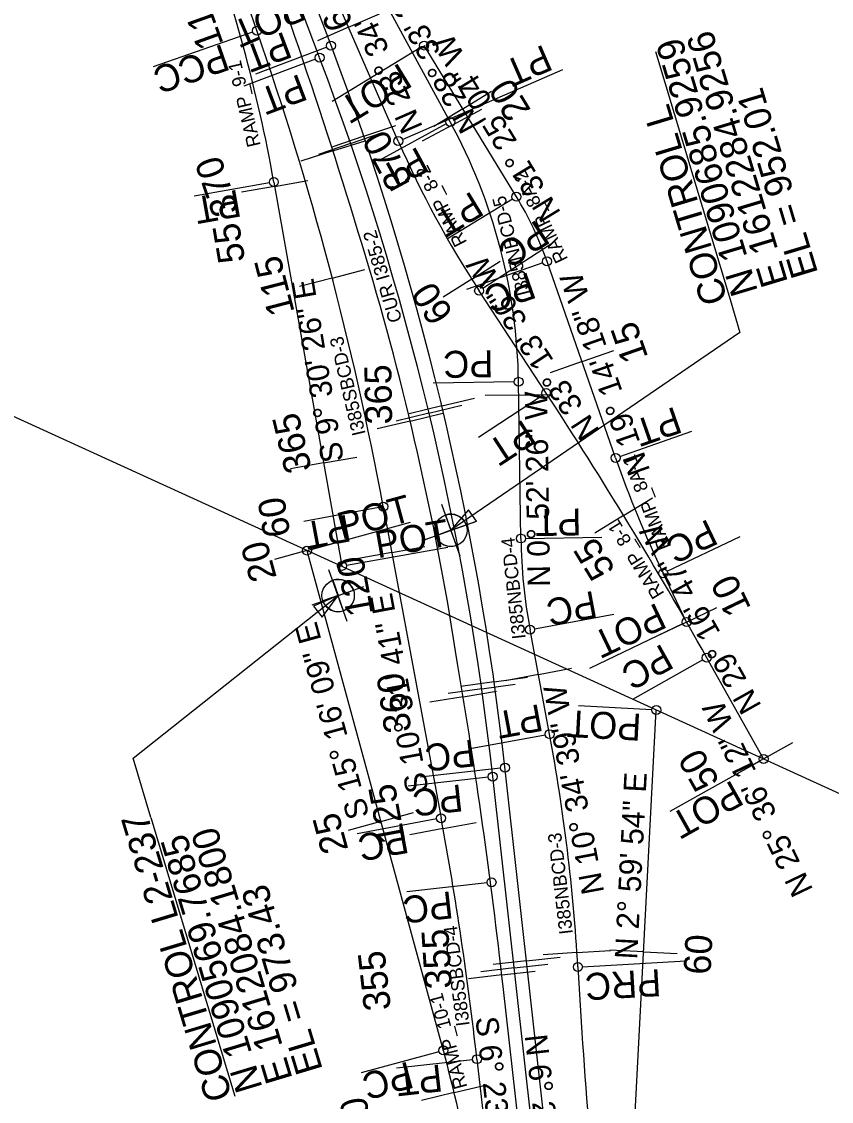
# Model space of a CAD drawing. Extents: x 1603447 to 1622636, y 1083818 to 1103958.
# Drawn here: x 1611521 to 1612962, y 1089669 to 1091591 of the extents above; entities that cross this region are included whole.
import ezdxf

# ---------------------------------------------------------------- set-up
doc = ezdxf.new("R2010")
doc.units = 0
for name, color, linetype in [('Level 1', 7, 'Continuous'), ('RD_HC_Points', 7, 'Continuous'), ('RD_HC_SUR_Bearing_TX400', 7, 'Continuous'), ('RD_HC_SUR_CL400', 7, 'Continuous'), ('RD_HC_SUR_PC_PT_400', 7, 'Continuous'), ('RD_HC_SUR_Tic400', 7, 'Continuous'), ('RD_HC_SUR_TX_Sta400', 7, 'Continuous'), ('RD_SHT_Misc1', 7, 'Continuous'), ('RD_TX_Misc1', 7, 'Continuous')]:
    doc.layers.add(name, color=color, linetype=linetype)

msp = doc.modelspace()

# ---------------------------------------------------------------- linework, layer by layer
at = {"layer": 'RD_HC_Points'}
for p, q in [((1612649, 1091538.2), (1612781.9, 1091096.5)), ((1611750.7, 1090174.9), (1611900, 1089678.9))]:
    msp.add_line(p, q, dxfattribs=at)
for points in [[(1612781.9, 1091096.5), (1612799.5, 1091038.1), (1612284.9, 1090685.9)], [(1611750.7, 1090174.9), (1611719, 1090280.2), (1612084.2, 1090569.8)]]:
    msp.add_lwpolyline(points, dxfattribs=at)
for points in [[(1612316.2, 1090722.4), (1612284.9, 1090685.9), (1612330.2, 1090701.9)], [(1612055.6, 1090531.2), (1612084.2, 1090569.8), (1612040.1, 1090550.7)]]:
    msp.add_lwpolyline(points, close=True, dxfattribs=at)
at = {"layer": 'RD_HC_SUR_CL400'}
for p, q in [((1612051.1, 1091527.2), (1611564.1, 1092814.8)), ((1612071.1, 1091550.5), (1611593.4, 1092813.6)), ((1612283.8, 1091412.9), (1612117.9, 1091717.6)), ((1612191.2, 1091378.6), (1612063.1, 1091672.2)), ((1612401.6, 1091279.6), (1612237.2, 1091548.8)), ((1611969.7, 1091305.8), (1612090.9, 1090622.6)), ((1613356.7, 1090043.6), (1610810.9, 1091205.6)), ((1612578.1, 1090814.8), (1612456, 1091164.6)), ((1612454.5, 1090930.1), (1612335.2, 1091112.3)), ((1612409.5, 1090671.3), (1612405.3, 1090950.2)), ((1612164.4, 1090728), (1612267.5, 1090173.4)), ((1612028.5, 1090649.9), (1612271.4, 1089760)), ((1612704.5, 1090522.6), (1612662.8, 1090609.5)), ((1612460.6, 1090323), (1612425.8, 1090508.9)), ((1612841.5, 1090278.8), (1612740.4, 1090459.1)), ((1612608.3, 1089558.3), (1612650.6, 1090365.9)), ((1612533.6, 1088900.6), (1612380.9, 1090265.1)), ((1612510.5, 1088898), (1612359.5, 1090247.4)), ((1612487.4, 1088895.4), (1612377.9, 1089874.1)), ((1612331.3, 1089744.5), (1612349.6, 1089581.2))]:
    msp.add_line(p, q, dxfattribs=at)
for centre, radius, start, end in [((1602552.7, 1088307.1), 10000, 16.52176, 20.71665), ((1602552.7, 1088307.1), 9939.5, 19.19672, 20.71665), ((1609311.2, 1090834.2), 2700, 10.058, 20.5018), ((1606462.1, 1089668.2), 5800, 10.52808, 19.19672), ((1607113.8, 1089675.6), 5300, 6.3858, 20.7167), ((1607115.5, 1089660.5), 5276.8, 6.3858, 20.7167), ((1611405.4, 1090934.9), 1000, 0.8738, 28.5554), ((1613841, 1092098.6), 1800, 203.5791, 213.2266), ((1611889.5, 1090966.9), 600, 19.2382, 31.4178), ((1607115.5, 1089660.5), 5240.8, 8.6501, 16.5218), ((1605762.5, 1086546.5), 8000, 29.27962, 33.2266), ((1614466.4, 1091473.8), 2000, 199.2382, 205.6034), ((1613374.4, 1090686.1), 965, 180.8738, 190.5776), ((1602439.9, 1088761.9), 10000, 6.3858, 9.71157), ((1609241.2, 1089721.8), 3275, 3.2705, 10.5776), ((1606368.5, 1089077.1), 6000, 6.3858, 10.52808), ((1623992.1, 1090564.7), 11500, 183.27051, 186.3858), ((1609859.7, 1089101.6), 2500, 10.1713, 15.269)]:
    msp.add_arc(centre, radius, start, end, dxfattribs=at)
at = {"layer": 'RD_HC_SUR_PC_PT_400'}
for p, q in [((1611932, 1091572.7), (1611755, 1091511.1)), ((1612063.8, 1091545.8), (1611936.8, 1091497.8)), ((1612230.4, 1091544.6), (1612073.8, 1091449)), ((1612043.6, 1091524.3), (1611916.5, 1091476.3)), ((1612198.6, 1091381.8), (1612484.1, 1091506.4)), ((1612276.7, 1091409.1), (1612157.4, 1091344.2)), ((1611961.9, 1091304.4), (1611828.1, 1091280.7)), ((1612394.7, 1091275.5), (1612278.8, 1091204.7)), ((1612341.9, 1091116.7), (1612462.2, 1091195.4)), ((1612448.5, 1091161.9), (1612312.7, 1091114.6)), ((1612397.3, 1090950.1), (1612253.5, 1090947.9)), ((1612447.9, 1090925.8), (1612334.2, 1090851.3)), ((1612585.6, 1090817.4), (1612713.9, 1090862.2)), ((1612156.6, 1090726.5), (1612023, 1090701.7)), ((1612036.2, 1090652), (1612213.1, 1090700.3)), ((1612670, 1090613), (1612799.6, 1090675.1)), ((1612098.8, 1090624), (1612279.4, 1090656)), ((1612417.5, 1090671.5), (1612553.4, 1090673.5)), ((1612433.7, 1090510.4), (1612575, 1090536.8)), ((1612697.2, 1090519.1), (1612531.8, 1090439.8)), ((1612733.4, 1090455.2), (1612608, 1090384.9)), ((1612642.6, 1090366.3), (1612512, 1090373.2)), ((1612452.7, 1090321.5), (1612319.2, 1090296.6)), ((1612834.6, 1090274.9), (1612674.6, 1090185.2)), ((1612373.2, 1090262.4), (1612230.3, 1090246.4)), ((1612351.6, 1090246.5), (1612208.7, 1090230.6)), ((1612259.6, 1090172), (1612118.3, 1090145.7)), ((1612349.2, 1090058.5), (1612206.3, 1090042.5)), ((1612518.9, 1089909.1), (1612703, 1089919.6)), ((1612263.7, 1089757.8), (1612125, 1089720)), ((1612323.3, 1089743.6), (1612188.3, 1089728.5))]:
    msp.add_line(p, q, dxfattribs=at)
for centre in [(1611939.6, 1091575.3), (1612071.3, 1091548.6), (1612237.2, 1091548.8), (1612051.1, 1091527.2), (1612283.8, 1091412.9), (1612191.2, 1091378.6), (1611969.7, 1091305.8), (1612401.6, 1091279.6), (1612456, 1091164.6), (1612335.2, 1091112.3), (1612405.3, 1090950.2), (1612454.5, 1090930.1), (1612578.1, 1090814.8), (1612164.4, 1090728), (1612409.5, 1090671.3), (1612028.5, 1090649.9), (1612090.9, 1090622.6), (1612662.8, 1090609.5), (1612704.5, 1090522.6), (1612425.8, 1090508.9), (1612740.4, 1090459.1), (1612650.6, 1090365.9), (1612460.6, 1090323), (1612841.5, 1090278.8), (1612359.5, 1090247.4), (1612381.1, 1090263.3), (1612267.5, 1090173.4), (1612357.2, 1090059.4), (1612510.9, 1089908.6), (1612271.4, 1089760), (1612331.3, 1089744.5)]:
    msp.add_circle(centre, 8, dxfattribs=at)
at = {"layer": 'RD_HC_SUR_Tic400'}
for p, q in [((1612102.7, 1091581.4), (1612157.7, 1091605.4)), ((1611903.3, 1091590.1), (1611903.3, 1091590.1)), ((1612102.7, 1091581.4), (1612047.7, 1091557.4)), ((1612191.3, 1091582.8), (1612191.3, 1091582.8)), ((1612037.8, 1091562.3), (1612037.8, 1091562.3)), ((1612061.7, 1091575.3), (1612061.7, 1091575.3)), ((1612012, 1091550.9), (1612012, 1091550.9)), ((1612253.8, 1091521.5), (1612253.8, 1091521.5)), ((1611927.8, 1091511), (1611927.8, 1091511)), ((1611959.2, 1091518.1), (1611959.2, 1091518.1)), ((1611961, 1091518.7), (1611961, 1091518.7)), ((1611929.5, 1091493.6), (1611929.5, 1091493.6)), ((1612142.7, 1091489.8), (1612142.7, 1091489.8)), ((1612239.1, 1091495), (1612239.1, 1091495)), ((1612072.8, 1091468.6), (1612072.8, 1091468.6)), ((1612096.6, 1091481.6), (1612096.6, 1091481.6)), ((1612306, 1091436.1), (1612357.2, 1091467.4)), ((1612044, 1091456.1), (1612044, 1091456.1)), ((1612306, 1091436.1), (1612254.8, 1091404.9)), ((1612286.9, 1091407.1), (1612339.8, 1091435.5)), ((1611947.1, 1091412.9), (1611947.1, 1091412.9)), ((1611990.2, 1091423), (1611990.2, 1091423)), ((1611992.2, 1091423.7), (1611992.2, 1091423.7)), ((1612129.8, 1091387.3), (1612186.6, 1091406.7)), ((1612286.9, 1091407.1), (1612234, 1091378.8)), ((1611952.1, 1091396.2), (1611952.1, 1091396.2)), ((1612129.8, 1091387.3), (1612073, 1091367.9)), ((1612106.2, 1091374.3), (1612162.9, 1091393.8)), ((1612182.7, 1091398.1), (1612182.7, 1091398.1)), ((1612106.2, 1091374.3), (1612049.4, 1091354.9)), ((1612075, 1091361.1), (1612132.1, 1091379.4)), ((1612075, 1091361.1), (1612017.9, 1091342.7)), ((1612358.1, 1091350.8), (1612358.1, 1091350.8)), ((1612019.7, 1091327.4), (1612019.7, 1091327.4)), ((1612329.6, 1091316.8), (1612329.6, 1091316.8)), ((1611971.1, 1091298.1), (1611912, 1091287.6)), ((1611971.1, 1091298.1), (1612030.2, 1091308.5)), ((1612161.2, 1091292.3), (1612161.2, 1091292.3)), ((1612224.3, 1091307.2), (1612224.3, 1091307.2)), ((1612137.8, 1091279.5), (1612137.8, 1091279.5)), ((1612105.1, 1091265.7), (1612105.1, 1091265.7)), ((1612410, 1091265.3), (1612410, 1091265.3)), ((1612047.5, 1091231.4), (1612047.5, 1091231.4)), ((1612049.3, 1091232), (1612049.3, 1091232)), ((1612270.7, 1091218.6), (1612270.7, 1091218.6)), ((1612363.1, 1091222.6), (1612363.1, 1091222.6)), ((1611988.6, 1091199.6), (1611988.6, 1091199.6)), ((1612190.8, 1091196.8), (1612190.8, 1091196.8)), ((1612167.5, 1091184), (1612167.5, 1091184)), ((1612452.3, 1091174.9), (1612452.3, 1091174.9)), ((1612134.2, 1091170), (1612134.2, 1091170)), ((1612322, 1091132.8), (1612372.6, 1091165)), ((1612073.6, 1091134.9), (1612131.6, 1091150)), ((1612073.6, 1091134.9), (1612015.5, 1091119.7)), ((1612322, 1091132.8), (1612271.4, 1091100.6)), ((1612387.1, 1091125.5), (1612387.1, 1091125.5)), ((1612006, 1091101.1), (1612006, 1091101.1)), ((1612218.6, 1091100.8), (1612218.6, 1091100.8)), ((1612195.5, 1091088), (1612195.5, 1091088)), ((1612485.4, 1091080.5), (1612485.4, 1091080.5)), ((1612162, 1091074), (1612162, 1091074)), ((1612376.7, 1091049), (1612376.7, 1091049)), ((1612098, 1091037.9), (1612098, 1091037.9)), ((1612099.4, 1091038.4), (1612099.4, 1091038.4)), ((1612401.2, 1091026.6), (1612401.2, 1091026.6)), ((1612023.5, 1091002.7), (1612023.5, 1091002.7)), ((1612244.6, 1091004.2), (1612244.6, 1091004.2)), ((1612518.3, 1090986.1), (1612575, 1091005.8)), ((1612221.6, 1090991.5), (1612221.6, 1090991.5)), ((1612518.3, 1090986.1), (1612461.7, 1090966.3)), ((1612188.1, 1090977.4), (1612188.1, 1090977.4)), ((1612120.8, 1090940.5), (1612120.8, 1090940.5)), ((1612121.8, 1090941), (1612121.8, 1090941)), ((1612405.7, 1090926.7), (1612345.7, 1090925.8)), ((1612405.7, 1090926.7), (1612465.6, 1090927.6)), ((1612268.7, 1090907.2), (1612210.4, 1090893.2)), ((1612245.9, 1090894.5), (1612304.3, 1090908.5)), ((1612268.7, 1090907.2), (1612327.1, 1090921.1)), ((1612041, 1090904.2), (1612041, 1090904.2)), ((1612245.9, 1090894.5), (1612187.6, 1090880.4)), ((1612212.3, 1090880.4), (1612270.7, 1090894.4)), ((1612551.3, 1090891.6), (1612551.3, 1090891.6)), ((1612212.3, 1090880.4), (1612153.9, 1090866.4)), ((1612486.1, 1090881.6), (1612486.1, 1090881.6)), ((1612141.9, 1090842.8), (1612141.9, 1090842.8)), ((1612142.4, 1090843.1), (1612142.4, 1090843.1)), ((1612058.4, 1090805.7), (1612117.5, 1090816.2)), ((1612291.1, 1090809.7), (1612291.1, 1090809.7)), ((1612407.2, 1090826.7), (1612407.2, 1090826.7)), ((1612058.4, 1090805.7), (1611999.3, 1090795.3)), ((1612268.4, 1090797), (1612268.4, 1090797)), ((1612539.7, 1090797.2), (1612539.7, 1090797.2)), ((1612584.3, 1090797.3), (1612584.3, 1090797.3)), ((1612234.6, 1090782.9), (1612234.6, 1090782.9)), ((1612161.3, 1090744.9), (1612161.3, 1090744.9)), ((1612161.3, 1090744.7), (1612161.3, 1090744.7)), ((1612592.3, 1090712.2), (1612643.6, 1090743.4)), ((1612408.7, 1090726.7), (1612408.7, 1090726.7)), ((1612075.9, 1090707.3), (1612075.9, 1090707.3)), ((1612289, 1090699.2), (1612289, 1090699.2)), ((1612311.5, 1090711.8), (1612311.5, 1090711.8)), ((1612592.3, 1090712.2), (1612541.1, 1090681)), ((1612620.5, 1090704), (1612620.5, 1090704)), ((1612255.1, 1090685.1), (1612255.1, 1090685.1)), ((1612028.5, 1090649.9), (1612086.4, 1090665.7)), ((1612179.6, 1090646.4), (1612238.6, 1090657.3)), ((1612028.5, 1090649.9), (1611970.6, 1090634.1)), ((1612179.6, 1090646.4), (1612120.6, 1090635.4)), ((1612411.3, 1090626.8), (1612411.3, 1090626.8)), ((1612643.9, 1090626.5), (1612643.9, 1090626.5)), ((1612307.8, 1090601), (1612307.8, 1090601)), ((1612330.2, 1090613.6), (1612330.2, 1090613.6)), ((1612661.2, 1090612.7), (1612661.2, 1090612.7)), ((1612273.7, 1090586.8), (1612273.7, 1090586.8)), ((1612054.8, 1090553.4), (1612054.8, 1090553.4)), ((1612054.8, 1090553.4), (1612054.8, 1090553.4)), ((1612197.8, 1090548.3), (1612197.8, 1090548.3)), ((1612197.9, 1090548), (1612197.9, 1090548)), ((1612704.5, 1090522.6), (1612758.6, 1090548.5)), ((1612422.6, 1090527.5), (1612422.6, 1090527.5)), ((1612704.5, 1090522.6), (1612650.3, 1090496.6)), ((1612694.3, 1090540.2), (1612694.3, 1090540.2)), ((1612324.7, 1090502.4), (1612324.7, 1090502.4)), ((1612346.9, 1090515), (1612346.9, 1090515)), ((1612290.5, 1090488.2), (1612290.5, 1090488.2)), ((1612081.2, 1090456.9), (1612081.2, 1090456.9)), ((1612081.2, 1090456.9), (1612081.2, 1090456.9)), ((1612216.1, 1090450), (1612216.1, 1090450)), ((1612216.1, 1090449.7), (1612216.1, 1090449.7)), ((1612743.7, 1090453.2), (1612743.7, 1090453.2)), ((1612440.7, 1090429.1), (1612381.8, 1090418.1)), ((1612440.7, 1090429.1), (1612499.7, 1090440.2)), ((1612361.8, 1090416.1), (1612302.4, 1090407.7)), ((1612339.7, 1090403.5), (1612399.1, 1090412)), ((1612361.8, 1090416.1), (1612421.2, 1090424.5)), ((1612306.6, 1090389.5), (1612247.4, 1090379.8)), ((1612339.7, 1090403.5), (1612280.3, 1090395.1)), ((1612306.6, 1090389.5), (1612365.8, 1090399.3)), ((1612107.5, 1090360.5), (1612107.5, 1090360.5)), ((1612107.5, 1090360.5), (1612107.5, 1090360.5)), ((1612234.4, 1090351.7), (1612234.4, 1090351.7)), ((1612234.4, 1090351.4), (1612234.4, 1090351.4)), ((1612792.6, 1090366), (1612792.6, 1090366)), ((1612459.1, 1090330.8), (1612459.1, 1090330.8)), ((1612649, 1090334.9), (1612649, 1090334.9)), ((1612374.9, 1090316.9), (1612374.9, 1090316.9)), ((1612322.4, 1090290.8), (1612322.4, 1090290.8)), ((1612352.8, 1090304.4), (1612352.8, 1090304.4)), ((1612841.5, 1090278.8), (1612893.9, 1090308.1)), ((1612841.5, 1090278.8), (1612789.2, 1090249.4)), ((1612133.8, 1090264), (1612133.8, 1090264)), ((1612133.8, 1090264), (1612133.8, 1090264)), ((1612252.6, 1090253.3), (1612252.6, 1090253.3)), ((1612252.7, 1090253.1), (1612252.7, 1090253.1)), ((1612643.7, 1090235), (1612643.7, 1090235)), ((1612386.2, 1090217.6), (1612386.2, 1090217.6)), ((1612476.2, 1090232.3), (1612476.2, 1090232.3)), ((1612364.3, 1090205.1), (1612364.3, 1090205.1)), ((1612160.2, 1090167.5), (1612218.1, 1090183.3)), ((1612337.2, 1090191.9), (1612337.2, 1090191.9)), ((1612160.2, 1090167.5), (1612102.3, 1090151.7)), ((1612270.9, 1090154.8), (1612330, 1090165.6)), ((1612270.9, 1090154.8), (1612211.9, 1090144)), ((1612397.4, 1090118.2), (1612397.4, 1090118.2)), ((1612490.3, 1090133.3), (1612490.3, 1090133.3)), ((1612638.5, 1090135.1), (1612638.5, 1090135.1)), ((1612375.4, 1090105.7), (1612375.4, 1090105.7)), ((1612351, 1090092.8), (1612351, 1090092.8)), ((1612186.5, 1090071), (1612186.5, 1090071)), ((1612186.5, 1090071), (1612186.5, 1090071)), ((1612288.1, 1090056.3), (1612288.1, 1090056.3)), ((1612288.4, 1090056.6), (1612288.4, 1090056.6)), ((1612501.3, 1090033.9), (1612501.3, 1090033.9)), ((1612633.3, 1090035.3), (1612633.3, 1090035.3)), ((1612386.5, 1090006.3), (1612386.5, 1090006.3)), ((1612408.5, 1090018.8), (1612408.5, 1090018.8)), ((1612363.8, 1089993.7), (1612363.8, 1089993.7)), ((1612212.8, 1089974.6), (1612212.8, 1089974.6)), ((1612212.8, 1089974.6), (1612212.8, 1089974.6)), ((1612303.6, 1089957.5), (1612303.6, 1089957.5)), ((1612304.1, 1089957.8), (1612304.1, 1089957.8)), ((1612419.6, 1089919.5), (1612479.2, 1089926.1)), ((1612509.3, 1089934.3), (1612449.4, 1089930.4)), ((1612509.3, 1089934.3), (1612569.2, 1089938.1)), ((1612628.1, 1089935.4), (1612568.1, 1089938.6)), ((1612628.1, 1089935.4), (1612688, 1089932.3)), ((1612397.6, 1089906.9), (1612338, 1089900.2)), ((1612419.6, 1089919.5), (1612360, 1089912.8)), ((1612397.6, 1089906.9), (1612457.2, 1089913.6)), ((1612375.6, 1089894.4), (1612316, 1089887.6)), ((1612375.6, 1089894.4), (1612435.2, 1089901.2)), ((1612239.2, 1089878.1), (1612239.2, 1089878.1)), ((1612239.2, 1089878.1), (1612239.2, 1089878.1)), ((1612317.4, 1089858.4), (1612317.4, 1089858.4)), ((1612318, 1089858.8), (1612318, 1089858.8)), ((1612515.4, 1089834.4), (1612515.4, 1089834.4)), ((1612622.8, 1089835.6), (1612622.8, 1089835.6)), ((1612430.7, 1089820.1), (1612430.7, 1089820.1)), ((1612386.7, 1089795), (1612386.7, 1089795)), ((1612408.7, 1089807.5), (1612408.7, 1089807.5)), ((1612265.1, 1089781.5), (1612265.1, 1089781.5)), ((1612265.5, 1089781.6), (1612265.5, 1089781.6)), ((1612329.6, 1089759.2), (1612329.6, 1089759.2)), ((1612330.1, 1089759.5), (1612330.1, 1089759.5)), ((1612522.1, 1089734.7), (1612522.1, 1089734.7)), ((1612617.6, 1089735.7), (1612617.6, 1089735.7)), ((1612441.9, 1089720.7), (1612441.9, 1089720.7)), ((1612290.7, 1089684.9), (1612349, 1089698.9)), ((1612397.9, 1089695.6), (1612397.9, 1089695.6)), ((1612419.9, 1089708.2), (1612419.9, 1089708.2)), ((1612290.7, 1089684.9), (1612232.3, 1089670.9))]:
    msp.add_line(p, q, dxfattribs=at)
at = {"layer": 'RD_SHT_Misc1'}
for p, q in [((1612301.3, 1090640), (1612268.6, 1090731.9)), ((1612239, 1090669.6), (1612330.9, 1090702.3)), ((1612275.3, 1090713), (1612284.9, 1090685.9)), ((1612284.9, 1090685.9), (1612312, 1090695.6)), ((1612284.9, 1090685.9), (1612257.8, 1090676.3)), ((1612294.6, 1090658.8), (1612284.9, 1090685.9)), ((1612100.5, 1090523.8), (1612067.8, 1090615.7)), ((1612038.2, 1090553.4), (1612130.1, 1090586.1)), ((1612074.5, 1090596.9), (1612084.2, 1090569.8)), ((1612084.2, 1090569.8), (1612111.3, 1090579.4)), ((1612084.2, 1090569.8), (1612057.1, 1090560.1)), ((1612093.8, 1090542.7), (1612084.2, 1090569.8))]:
    msp.add_line(p, q, dxfattribs=at)
for centre in [(1612284.9, 1090685.9), (1612084.2, 1090569.8)]:
    msp.add_circle(centre, 28.8, dxfattribs=at)
for centre, start, end in [((1612284.9, 1090685.9), 19.573, 109.573), ((1612284.9, 1090685.9), 199.573, 289.573), ((1612084.2, 1090569.8), 19.573, 109.573), ((1612084.2, 1090569.8), 199.573, 289.573)]:
    msp.add_arc(centre, 28.8, start, end, dxfattribs=at)

# ---------------------------------------------------------------- texts
at = {"layer": 'Level 1'}
for s, rotation, p in [('65', 113.5791, (1612112.1, 1091587.3)), ('55', 99.5074, (1611919, 1091165.5)), ('115', 104.5102, (1612007, 1091074.6)), ('15', 109.2382, (1612636.6, 1090994)), ('365', 90.8738, (1612180.4, 1090874.5)), ('365', 103.5234, (1612037.6, 1090794.2)), ('55', 121.3798, (1612578.7, 1090616.1)), ('125', 100.5281, (1612204, 1090132.5)), ('25', 105.269, (1612102.6, 1090117.9)), ('355', 93.7198, (1612287, 1089870.9)), ('355', 96.3858, (1612178.4, 1089833.3))]:
    msp.add_text(s, height=48, rotation=rotation, dxfattribs=at).set_placement(p)
at = {"layer": 'RD_HC_Points'}
for s, p in [('N 1090685.9259', (1612831.7, 1091111.5)), ('E 1612284.9256', (1612885.3, 1091127.6)), ('EL = 952.01', (1612938.9, 1091143.8)), ('CONTROL L', (1612778.1, 1091095.4)), ('CONTROL L2-237', (1611896.2, 1089677.7)), ('N 1090569.7685', (1611949.8, 1089693.9)), ('E 1612084.1800', (1612003.4, 1089710)), ('EL = 973.43', (1612057.1, 1089726.1))]:
    msp.add_text(s, height=48, rotation=106.7478, dxfattribs=at).set_placement(p)
at = {"layer": 'RD_HC_SUR_Bearing_TX400'}
for s, rotation, p in [('N 23%%d 34\' 45" W', 113.5791, (1612235.5, 1091403.8)), ('N 28%%d 33\' 20" W', 118.5554, (1612339.3, 1091406.9)), ('N 31%%d 25\' 04" W', 121.4178, (1612481.6, 1091251)), ('N 33%%d 13\' 36" W', 123.2266, (1612550.8, 1090863.3)), ('N 19%%d 14\' 18" W', 109.2382, (1612640, 1090792.3)), ('S 9%%d 30\' 26" E', 99.5074, (1612094.5, 1090810.4)), ('N 0%%d 52\' 26" W', 90.8738, (1612461.6, 1090585.6)), ('N 29%%d 16\' 47" W', 119.2796, (1612838.7, 1090373.5)), ('S 10%%d 31\' 41" E', 100.5281, (1612245.4, 1090222.4)), ('S 15%%d 16\' 09" E', 105.269, (1612140.1, 1090178.1)), ('N 10%%d 34\' 39" W', 100.5776, (1612558, 1090041.9)), ('N 25%%d 36\' 12" W', 115.6034, (1612930.4, 1090046.1)), ('N 2%%d 59\' 54" E', 87.0015, (1612616.4, 1089921.5)), ('S 6%%d 23\' 09" E', 276.3858, (1612328.5, 1089818.3)), ('N 6%%d 23\' 09" W', 276.3858, (1612416.1, 1089786.6))]:
    msp.add_text(s, height=40, rotation=rotation, dxfattribs=at).set_placement(p)
at = {"layer": 'RD_HC_SUR_PC_PT_400'}
for s, rotation, p in [('POT', 203.5791, (1612011.9, 1091641.2)), ('PT', 200.7167, (1611988.7, 1091574.2)), ('PCC', 199.1967, (1611878.8, 1091552.1)), ('PT', 203.5791, (1612450.3, 1091551.3)), ('POT', 211.4178, (1612194.3, 1091519)), ('PT', 200.7167, (1612015.9, 1091498.7)), ('PT', 208.5554, (1612226.6, 1091369.7)), ('PT', 190.058, (1611906.1, 1091292.5)), ('PT', 211.4178, (1612322.2, 1091290.5)), ('PC', 213.2266, (1612438.3, 1091239.8)), ('PC', 199.2382, (1612424.2, 1091146.2)), ('PC', 180.8738, (1612360.1, 1091006.4)), ('PT', 199.2382, (1612684.1, 1090906.6)), ('PT', 213.2266, (1612414.1, 1090884.5)), ('POT', 15.269, (1612090.7, 1090668.9)), ('PT', 180.8738, (1612516.9, 1090724.8)), ('PT', 190.5281, (1612100.9, 1090714.1)), ('POT', 10.058, (1612154.6, 1090635.9)), ('PC', 205.6034, (1612743.2, 1090706.8)), ('PC', 190.5776, (1612539.5, 1090578.5)), ('POT', 205.6034, (1612651.7, 1090557.8)), ('PC', 209.2796, (1612661.6, 1090484.9)), ('PT', 190.5776, (1612442.8, 1090376.8)), ('POT', 177.0015, (1612625.1, 1090359.1)), ('PC', 186.3858, (1612325.2, 1090313.9)), ('PC', 186.3858, (1612303.2, 1090233.8)), ('POT', 209.2796, (1612786.3, 1090242.1)), ('PC', 190.5281, (1612204, 1090159.6)), ('PC', 186.3858, (1612285.7, 1090043.4)), ('PRC', 183.2705, (1612657.7, 1089904.8)), ('PC', 195.269, (1612209.3, 1089740.9)), ('PT', 186.3858, (1612266.9, 1089735.2))]:
    msp.add_text(s, height=48, rotation=rotation, dxfattribs=at).set_placement(p)
at = {"layer": 'RD_HC_SUR_TX_Sta400'}
for s, rotation, p in [('110', 109.7189, (1611880.7, 1091551.9)), ('20', 121.4178, (1612428.4, 1091433.6)), ('370', 118.1775, (1612218.2, 1091308.1)), ('370', 108.9525, (1611908.4, 1091254.6)), ('60', 122.4494, (1612290.7, 1091072.1)), ('60', 99.5074, (1611999.5, 1090677.5)), ('20', 105.269, (1611975.2, 1090601.8)), ('120', 100.5281, (1612147.5, 1090537.4)), ('10', 115.6034, (1612820.1, 1090547.3)), ('360', 98.0944, (1612214.8, 1090328.8)), ('50', 119.2796, (1612764.3, 1090239.1)), ('60', 87.0015, (1612747, 1089894)), ('30', 101.8655, (1612147.6, 1089610.3))]:
    msp.add_text(s, height=48, rotation=rotation, dxfattribs=at).set_placement(p)
at = {"layer": 'RD_TX_Misc1'}
for s, rotation, p in [('RAMP_9-1', 103.1467, (1611946.4, 1091371.2)), ('RAMP_8-2', 117.0709, (1612314.2, 1091198.4)), ('RAMP_8A-2', 115.6781, (1612494, 1091168.7)), ('I385NBCD-5', 104.4199, (1612426.6, 1091106.9)), ('CUR I385-2', 106.2524, (1612198.4, 1091059.6)), ('I385SBCD-3', 103.2644, (1612133.4, 1090857.5)), ('RAMP_8A-1', 111.2395, (1612676.9, 1090656.4)), ('RAMP_8-1', 121.8105, (1612665.6, 1090573.4)), ('I385NBCD-4', 96.4049, (1612418.2, 1090493.5)), ('I385NBCD-3', 96.6133, (1612502, 1089968)), ('I385SBCD-4', 97.3523, (1612318.5, 1089804.7)), ('RAMP_10-1', 104.8876, (1612314.3, 1089695))]:
    msp.add_text(s, height=24, rotation=rotation, dxfattribs=at).set_placement(p)

doc.saveas('drawing.dxf')
